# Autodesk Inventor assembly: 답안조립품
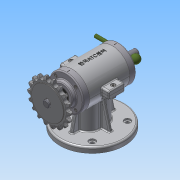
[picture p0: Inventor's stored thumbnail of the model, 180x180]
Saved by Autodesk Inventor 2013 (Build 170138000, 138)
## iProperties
Created: 2016-04
Part Number: 답안조립품
Document SubType Name: Assembly
Designer: Administrator
Mass: 1745.74 g
Surface Area: 1440.72 cm^2
Volume: 462.013 cm^3
Density: 3.77856 g/cm^3
Author: Administrator
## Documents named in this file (19)
- C:\Users\Administrator\Desktop\360408V1017\답안조립품.iam
- C:\Users\Administrator\Desktop\360408V1017\본체.ipt
- C:\Users\Administrator\Desktop\360408V1017\너트 M4.ipt
- C:\Users\Administrator\Desktop\360408V1017\뒤커버.ipt
- C:\Users\Administrator\Desktop\360408V1017\레바.ipt
- C:\Users\Administrator\Desktop\360408V1017\멈춤나사 M3x8.ipt
- C:\Users\Administrator\Desktop\360408V1017\베어링 6201.ipt
- C:\Users\Administrator\Desktop\360408V1017\베어링 6202.ipt
- C:\Users\Administrator\Desktop\360408V1017\본체상부커버.ipt
- C:\Users\Administrator\Desktop\360408V1017\볼트 M3x0.5x8.ipt
- C:\Users\Administrator\Desktop\360408V1017\볼트 M4 x 16.ipt
- C:\Users\Administrator\Desktop\360408V1017\스프로킷.ipt
- C:\Users\Administrator\Desktop\360408V1017\스프링.ipt
- C:\Users\Administrator\Desktop\360408V1017\슬라이드.ipt
- C:\Users\Administrator\Desktop\360408V1017\앞커버.ipt
- C:\Users\Administrator\Desktop\360408V1017\오일실 12 22 7.ipt
- C:\Users\Administrator\Desktop\360408V1017\와셔 ST 4-100.ipt
- C:\Users\Administrator\Desktop\360408V1017\키 4 x 4 x 18.ipt
- C:\Users\Administrator\Desktop\360408V1017\편심축.ipt
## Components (6 placed, 3 different names)
1. ISO 4032 M4:1
2. ISO 4762 M4 x 16:1
3. ISO 7091 ST 4 - 100 HV:1
4. ISO 4762 M4 x 16:2
5. ISO 4032 M4:2
6. ISO 7091 ST 4 - 100 HV:2
